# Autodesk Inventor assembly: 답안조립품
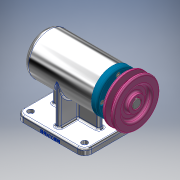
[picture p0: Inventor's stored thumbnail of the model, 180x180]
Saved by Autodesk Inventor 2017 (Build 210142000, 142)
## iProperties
Part Number: 답안조립품
Material: 일반
Document SubType Name: Assembly
Designer: 7-1
Author: 7-1
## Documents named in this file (12)
- C:\Users\7-1\Desktop\701004V1009\답안조립품.iam
- C:\Users\7-1\Desktop\701004V1009\본체.ipt
- C:\Users\7-1\Desktop\701004V1009\커버.ipt
- C:\Users\7-1\Desktop\701004V1009\축.ipt
- C:\Users\7-1\Desktop\701004V1009\베어링 6004.ipt
- C:\Users\7-1\Desktop\701004V1009\어댑터슬리브.ipt
- C:\Users\7-1\Desktop\701004V1009\베어링 51202.ipt
- C:\Users\7-1\Desktop\701004V1009\오일 실.ipt
- C:\Users\7-1\Desktop\701004V1009\키 5 x 5 x 16.ipt
- C:\Users\7-1\Desktop\701004V1009\V벨트풀리.ipt
- C:\Users\7-1\Desktop\701004V1009\멈춤나사 M3.ipt
- C:\Users\7-1\Desktop\701004V1009\볼트 M4.ipt
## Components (1 placed, 1 different names)
1. V벨트풀리:1
